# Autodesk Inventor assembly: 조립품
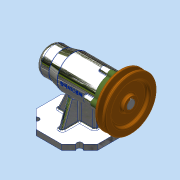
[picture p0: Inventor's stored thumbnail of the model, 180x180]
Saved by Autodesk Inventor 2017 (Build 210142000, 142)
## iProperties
Created: 2019-12
Part Number: 조립품
Document SubType Name: Assembly
Designer: 5-15-le-1
Author: 5-15-le-1
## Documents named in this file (12)
- C:\Users\5-15-le-1\Desktop\491204V1002\조립품.iam
- C:\Users\5-15-le-1\Desktop\491204V1002\본체.ipt
- C:\Users\5-15-le-1\Desktop\491204V1002\V벨트풀리.ipt
- C:\Users\5-15-le-1\Desktop\491204V1002\멈춤나사 M3.ipt
- C:\Users\5-15-le-1\Desktop\491204V1002\베어링 6004.ipt
- C:\Users\5-15-le-1\Desktop\491204V1002\베어링 51202.ipt
- C:\Users\5-15-le-1\Desktop\491204V1002\볼트 M4.ipt
- C:\Users\5-15-le-1\Desktop\491204V1002\어댑터슬리브.ipt
- C:\Users\5-15-le-1\Desktop\491204V1002\오일 실.ipt
- C:\Users\5-15-le-1\Desktop\491204V1002\축.ipt
- C:\Users\5-15-le-1\Desktop\491204V1002\커버.ipt
- C:\Users\5-15-le-1\Desktop\491204V1002\키 5 x 5 x 16.ipt
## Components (1 placed, 1 different names)
1. V벨트풀리:1
